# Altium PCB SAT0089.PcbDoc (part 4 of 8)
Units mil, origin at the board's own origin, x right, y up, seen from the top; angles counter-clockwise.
Board outline 4075 x 2715 mil, 6 copper layers (Top Layer, InternalPlane1, MidLayer1, Internal Plane 3, InternalPlane2, Bottom Layer), stack 67.4 mil thick; 538 components, 405 nets, 1716 pads, 1236 vias.
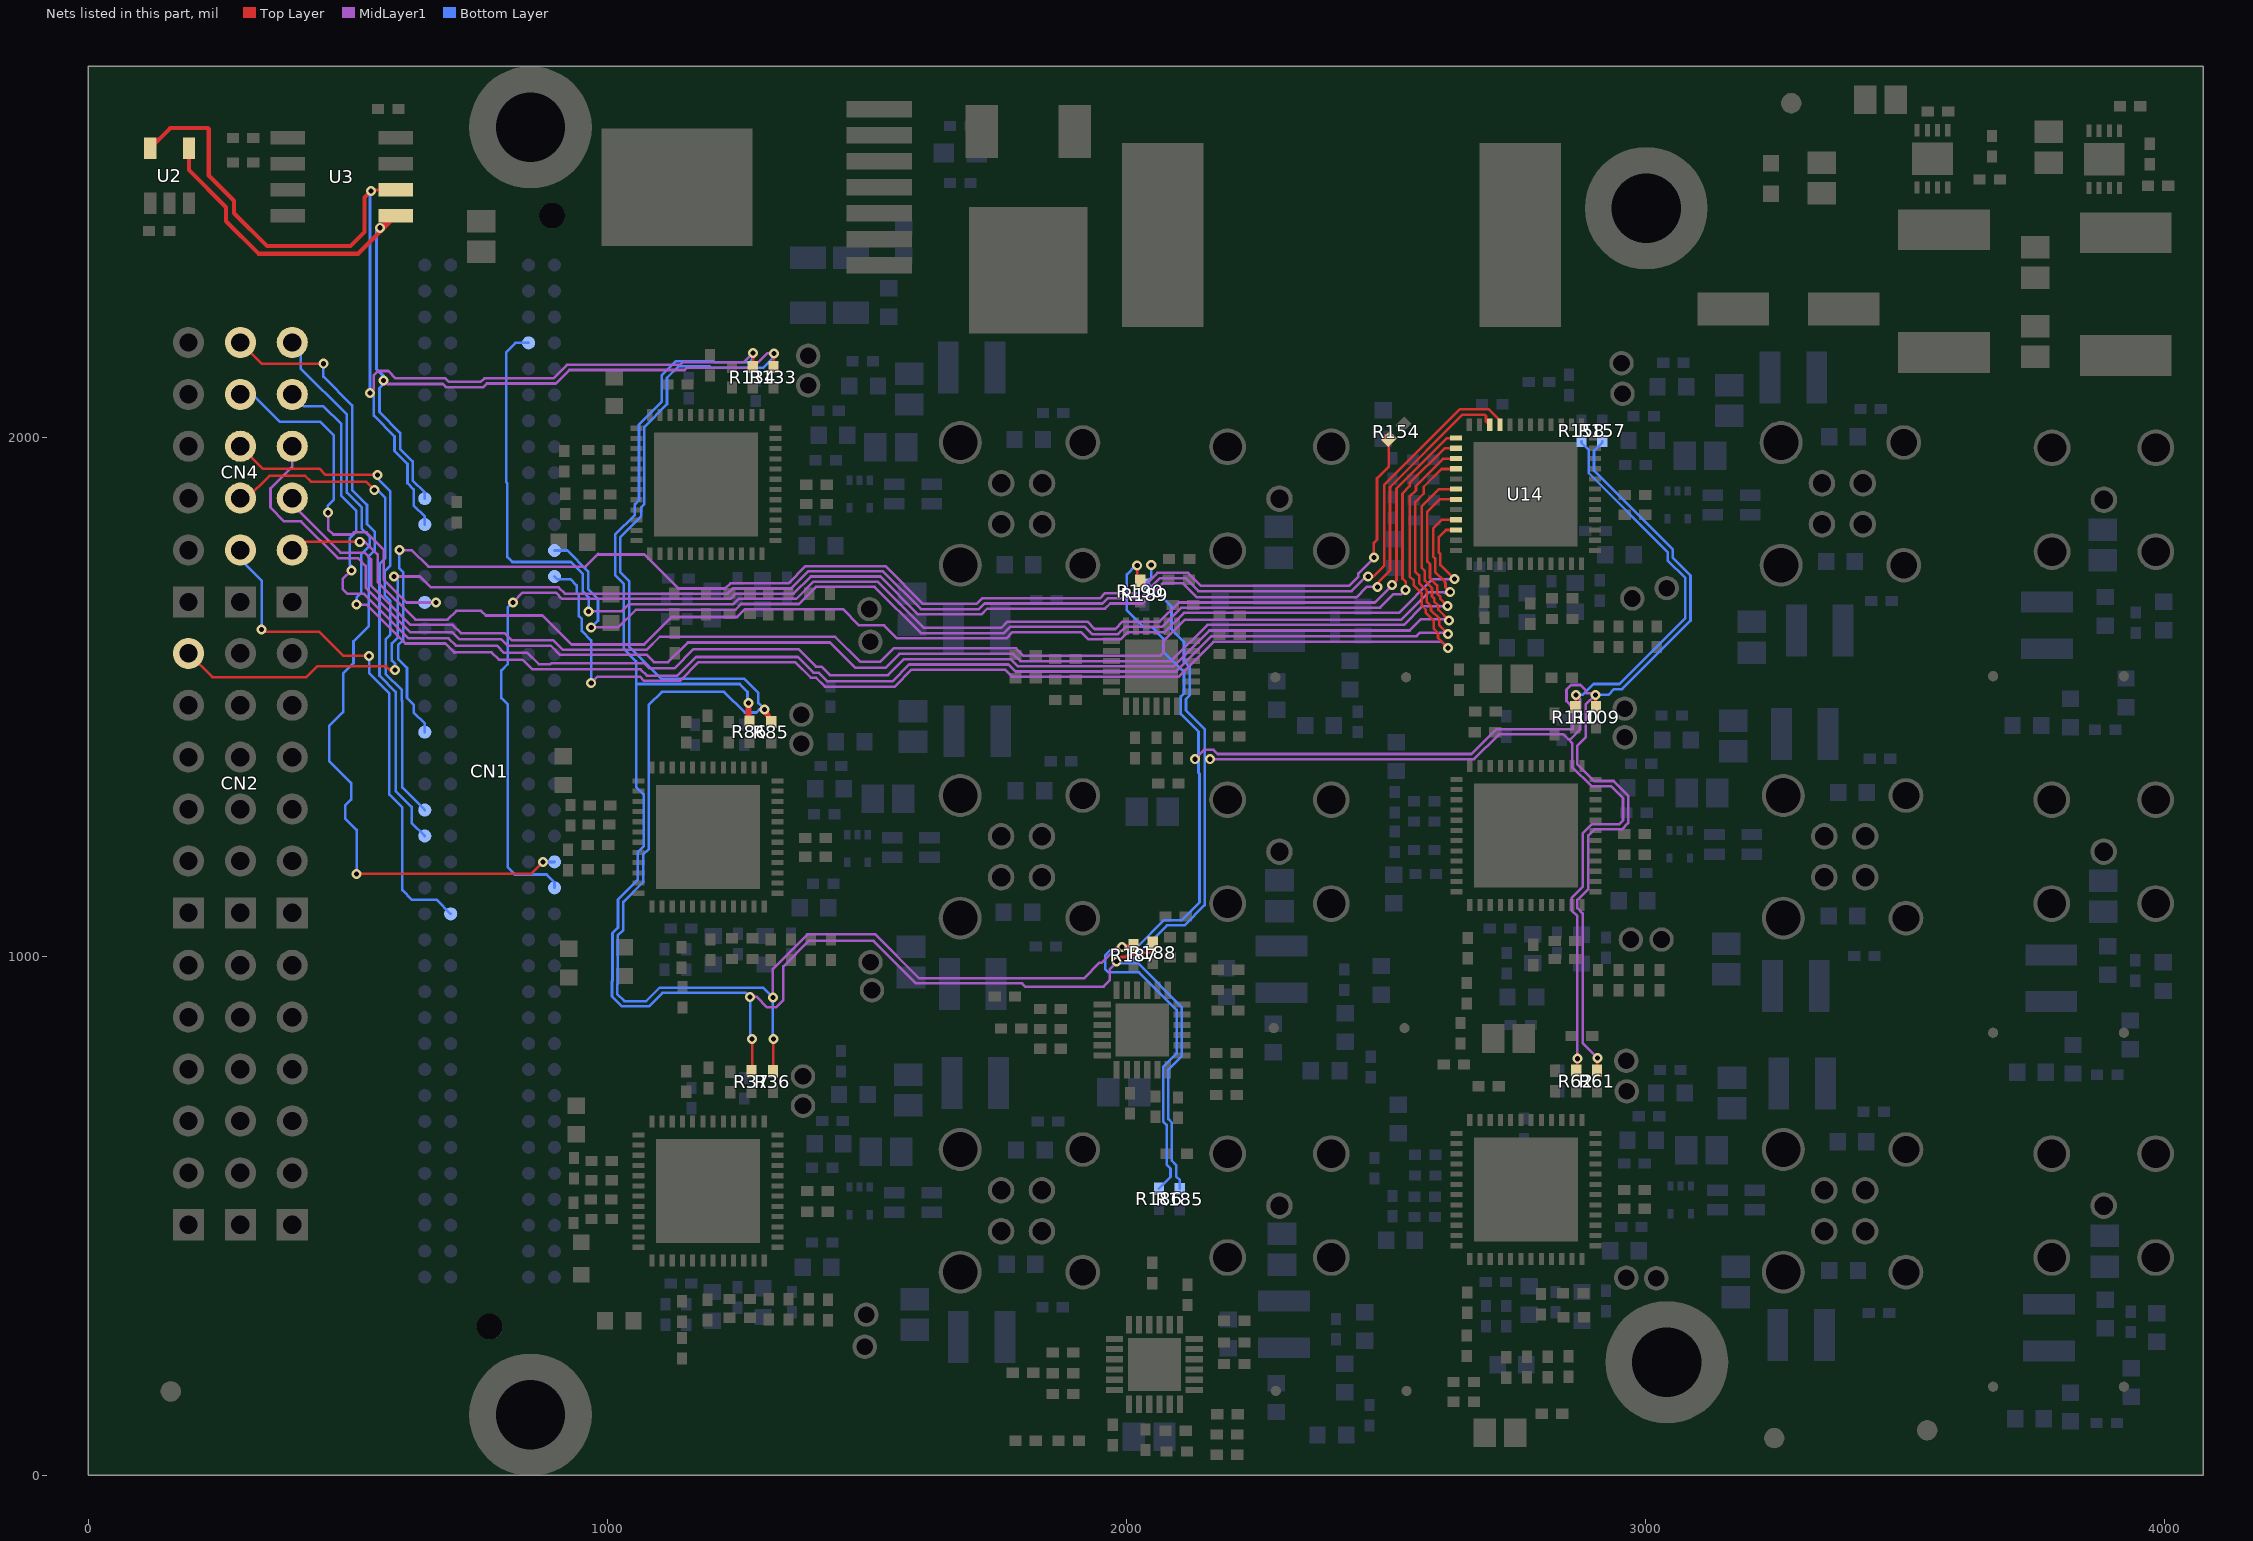
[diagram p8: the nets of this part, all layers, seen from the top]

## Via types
v1: diameter 19.29, hole 9.84, Top Layer to Bottom Layer, tented both sides, 1155 vias
v2: diameter 19.68, hole 7.87, Top Layer to Bottom Layer, tented both sides, 80 vias
v3: diameter 22, hole 10, Top Layer to Bottom Layer, tented both sides, 1 vias

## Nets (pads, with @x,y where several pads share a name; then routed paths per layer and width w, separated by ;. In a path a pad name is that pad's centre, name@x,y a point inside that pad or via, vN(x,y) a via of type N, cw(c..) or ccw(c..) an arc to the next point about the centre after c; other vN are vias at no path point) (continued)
CAM6_D2: CN4.2 U14.22 | length 2617.3
  Top Layer w5: CN4.2@393,1783 407,1797 CN4.2@407,1799 ; CN4.2@407,1800 CN4.2@407,1799 ; v1(523,1799) CN4.2@407,1799 ; v1(2632,1727) 2605,1754 2605,1775 2602,1778 2602,1808 2615.63,1821.63 U14.22@2635.14,1821.63
  MidLayer1 w5: v1(523,1799) 533,1799 557.5,1774.5 557.5,1721.5 630,1649 692,1649 709,1666 757,1666 766,1657 875,1657 931,1601 1071,1601 1124,1654 1250,1654 1265,1669 1454,1669 1485,1638 1533,1638 1558,1613 1769,1613 1781,1625 1913,1625 1927,1611 1989,1611 2003,1625 2074,1625 2111,1662 2525,1662 2590,1727 v1(2632,1727)
CAM6_D2_CAM3_D10: CN1.55 CN4.8 | length 987.9
  Top Layer w5: v1(334,1630) 338,1626 444.5,1626 491.5,1579 v1(541,1579)
  Bottom Layer w5: CN4.8@293,1783 293,1765 334,1724 v1(334,1630) ; v1(541,1579) 541,1546 580,1507 580,1312 605,1287 605,1128 624,1109 671.43,1109 CN1.55@698.27,1082.17
CAM6_D3: CN4.3 U14.21 | length 2697.7
  Top Layer w5: v1(2624,1702) 2615,1711 2615,1719 2614,1720 2614,1722 2595,1741 2595,1767 2591,1771 2591,1825 2607.32,1841.32 U14.21@2635.14,1841.31
  MidLayer1 w5: CN4.3@393,1883 393,1871 486,1778 532,1778 545,1765 545,1715 621,1639 702,1639 718,1623 802,1623 816,1609 896,1609 914,1591 1076,1591 1101,1616 1439,1616 1487,1568 1526,1568 1551.5,1593.5 1787.5,1593.5 1802,1579 2065,1579 2072,1586 2072,1608 2113,1649 2530,1649 2583,1702 v1@2621,1702 ; v1@2615,1700 2619,1700 v1@2621,1702 ; v1@2621,1702 v1(2624,1702) 2624,1703 2622,1703 v1@2621,1702
CAM6_D3_CAM3_D11: CN1.18 CN4.9 | length 1006.7
  Top Layer w5: CN4.9@293,1883 306,1883 349,1926 418,1926 429,1915 535,1915 v1(551,1899)
  Bottom Layer w5: v1(551,1899) 557,1899 572,1884 572,1767 561,1756 561,1541 592,1510 592,1319 623,1288 623,1257.43 CN1.18@648.27,1232.17
CAM6_D4: CN4.4 U14.19 | length 2917.5
  Top Layer w5: v1(2619,1675) 2604.5,1689.5 2604.5,1693.5 2599,1699 2599,1715 2585,1729 2585,1756 2580,1761 2580,1857 2603.68,1880.68 U14.19@2635.14,1880.68
  MidLayer1 w5: CN4.4@393,1983 393,1944 351,1902 351,1865 377.5,1838.5 410,1838.5 481,1767.5 519.5,1767.5 534.5,1752.5 534.5,1710.5 620,1625 701,1625 715,1611 796,1611 808,1599 891,1599 909,1581 1076,1581 1090,1567 1117,1567 1155,1605 1429,1605 1478,1556 1536,1556 1563,1583 1782,1583 1796,1569 2086,1569 2156,1639 2535,1639 2571,1675 v1(2619,1675) v1@2619,1676 ; v1@2615,1676 v1@2619,1676 ; v1@2620,1676 v1@2619,1676
CAM6_D4_CAM4_VS: CN1.19 CN4.10 | length 987
  Top Layer w5: CN4.10@293,1983 336,1940 445,1940 457,1928 v1(557,1928)
  Bottom Layer w5: v1(557,1928) 557,1921 582,1896 582,1753 571,1742 571,1696 582,1685 582,1620 573,1611 573,1544 604,1513 604,1493 605,1492 605,1325.43 CN1.19@648.27,1282.17
CAM6_D5: CN4.5 U14.18 | length 3076.2
  Top Layer w5: v1(2622,1647) 2601,1668 2601,1676 2593,1684 2593,1690 2589,1694 2589,1710 2575,1724 2575,1743 2569,1749 2569,1867 2601.84,1899.84 2635.14,1899.84 U14.18@2635.14,1900.37
  MidLayer1 w5: v1(507,1744) 490,1727 490,1708 499.5,1698.5 531.5,1698.5 617,1613 694,1613 708,1599 787,1599 801,1585 846,1585 868,1563 890,1563 892,1565 1071,1565 1081,1555 1129,1555 1166,1592 1368.5,1592 1402,1558.5 1412.5,1558.5 1429,1542 1541,1542 1572,1573 1777,1573 1791,1559 2091,1559 2160,1628 2546,1628 2568,1650 2619,1650 v1@2621,1648 ; v1@2621,1648 v1(2622,1647) 2622,1648 v1@2621,1648
  Bottom Layer w5: CN4.5@393,2083 416,2060 453,2060 487.5,2025.5 487.5,1887.5 516.5,1858.5 516.5,1818.5 504,1806 504,1755 507,1752 v1(507,1744)
CAM6_D5_CAM4_D10: CN1.27 CN4.11 | length 724.6
  MidLayer1 w5: v1(462,1855) 462,1823 472,1813 508,1813 512,1817 536,1817 569,1784 569,1726 613,1682 v1(670,1682)
  Bottom Layer w5: CN4.11@293,2083 316,2083 369,2030 447,2030 473,2004 473,1880 461,1868 461,1856 v1(462,1855) ; CN1.27@648.27,1682.17 669.83,1682.17 v1(670,1682)
CAM6_D6: CN4.6 U14.16 | length 3216.5
  Top Layer w5: v1(2620,1621) 2603,1638 2603,1651 2587,1667 2587,1675 2579,1683 2579,1705 2564,1720 2564,1734 2557,1741 2557,1876 2573,1892 2573,1905 2607.21,1939.21 2635.14,1939.21 U14.16@2635.14,1939.74
  MidLayer1 w5: v1(517,1678) 536,1678 611,1603 688,1603 705.5,1585.5 706,1586 777,1586 791,1572 837,1572 856,1553 1064,1553 1076,1541 1135,1541 1171,1577 1367,1577 1397,1547 1407,1547 1424,1530 1549,1530 1581.5,1562.5 1773,1562.5 1786.5,1549 2096,1549 2164,1617 2559,1617 2566,1624 2617,1624 v1(2620,1621)
  Bottom Layer w5: CN4.6@393,2183 409,2167 409,2133 498,2044 498,1894 527,1865 527,1824 542,1809 542,1791 526,1775 526,1701 517,1692 v1(517,1678)
CAM6_D6_CAM4_D11: CN1.137 CN4.12 | length 1659.8
  Top Layer w5: CN4.12@293,2183 334,2142 v1(453,2142) ; v1(517,1159) 853,1159 v1(876,1182)
  Bottom Layer w5: v1(453,2142) 453,2117 508.5,2061.5 508.5,1898.5 537,1870 537,1833 552,1818 552,1783 540,1771 540,1636 511,1607 511,1565 491,1545 491,1471 464,1444 464,1377 506.5,1334.5 506.5,1302.5 495,1291 495,1266 517,1244 v1(517,1159) ; v1(876,1182) 898.1,1182 CN1.137@898.27,1182.17
CAM6_D7: CN1.148 U14.15 | length 2442.6
  Top Layer w5: v1(2620,1594) 2600.5,1613.5 2600.5,1623 2592,1631.5 2592,1647 2577,1662 2577,1668 2569,1676 2569,1700 2554,1715 2554,1724 2546,1732 2546,1886 2558,1898 2558,1906.9 2610,1958.9 2635.14,1958.9 U14.15@2635.14,1959.43
  MidLayer1 w5: v1(969,1527) 981,1539 1063,1539 1071,1531 1140,1531 1176,1567 1362,1567 1392,1537 1402,1537 1419,1520 1554,1520 1586.5,1552.5 1766,1552.5 1779.5,1539 2101,1539 2168,1606 2608,1606 v1(2620,1594)
  Bottom Layer w5: CN1.148@898.27,1732.17 903.43,1727 929,1727 941,1715 941,1700 945,1696 945,1656 951,1650 951,1627 969,1609 v1(969,1527)
CAM6_D8: CN1.149 U14.14 | length 2218
  Top Layer w5: v1(2538,1706) 2538,1722 2532,1728 2532,1892 2546,1906 2546,1912 2613.11,1979.11 U14.14@2635.14,1979.11
  MidLayer1 w5: v1(969,1634) 1021,1634 1055,1668 1247,1668 1258,1679 1369,1679 1402,1712 1515,1712 1604,1623 1764,1623 1776,1635 1920,1635 1934,1621 1984,1621 1998,1635 2069,1635 2106,1672 2489,1672 2515,1698 2530,1698 v1(2538,1706)
  Bottom Layer w5: CN1.149@898.27,1782.17 922.83,1782.17 963,1742 963,1708 982,1689 982,1647 v1(969,1634)
CAM6_D9: CN1.117 U14.13 | length 2680.8
  Top Layer w5: v1(2512,1716) 2520.5,1724.5 2520.5,1901.5 2617.8,1998.8 U14.13@2635.14,1998.8
  MidLayer1 w5: v1(964,1665) 1027.5,1665 1041,1678.5 1242.5,1678.5 1253,1689 1364,1689 1397,1722 1521,1722 1610,1633 1759,1633 1771,1645 1925,1645 1939,1631 1979,1631 1993,1645 2064,1645 2101,1682 2479,1682 2512,1715 v1(2512,1716)
  Bottom Layer w5: CN1.117@848.27,2182.17 823.17,2182.17 805,2164 805,1914 807.5,1911.5 807.5,1769.5 817,1760 930,1760 953,1737 953,1703 964,1692 v1(964,1665)
CAM6_HS: CN1.136 U14.10 | length 2881.5
  Top Layer w5: v1(2484,1712) 2484,1720 2508,1744 2508,1905 2509,1905 2648,2044 2690,2044 2693,2041 2693,2030.96 2699.84,2024.12 2700.1,2023.86 U14.10@2700.1,2024.39
  MidLayer1 w5: v1(818,1682) 837,1701 901,1701 913,1689 1237,1689 1247,1699 1359,1699 1392,1732 1526,1732 1599,1659 1721,1659 1732,1670 1959,1670 1969,1680 2031,1680 2070,1719 2109,1719 2136,1692 2443,1692 2463,1712 v1(2484,1712) 2484,1709 v1@2486,1707
  Bottom Layer w5: v1(818,1682) 808,1672 808,1563 796,1551 796,1498 808,1486 808,1172 822,1158 883,1158 898.27,1142.73 CN1.136@898.27,1132.17
CAM6_PCLK: CN1.22 R154.1 | length 2681.9
  Top Layer w5: v1@2475,1771 v1(2477,1769) ; v1@2479,1765 2478,1764 2474,1764 2477,1767 v1(2477,1769) ; R154.1@2499,2003.72 2505.86,1996.86 2505.86,1943.86 2483,1921 2483,1803 2477,1797 v1(2477,1769)
  MidLayer1 w5: v1(599.5,1783) 623,1783 655,1751 958,1751 982.5,1775.5 983.5,1774.5 1071.5,1774.5 1137,1709 1227,1709 1237,1719 1349,1719 1382,1752 1536,1752 1608.5,1679.5 1711.5,1679.5 1722,1690 1949,1690 1959,1700 2021,1700 2060,1739 2119,1739 2144,1714 2429,1714 2447,1732 2447,1738 2477,1768 v1(2477,1769)
  Bottom Layer w5: v1(599.5,1783) 599.5,1782.5 599,1782 599,1748 607,1740 607,1610 597,1600 597,1573 614,1556 614,1498 627,1485 627,1470 648.27,1448.73 CN1.22@648.27,1432.17
CAM6_VS: CN2.18 U14.9 | length 3102.5
  Top Layer w5: v1(591,1552) 581,1552 574,1559 441,1559 420,1538 239,1538 CN2.18@194,1583 ; v1(2466,1732) 2476,1732 2497,1753 2497,1909 2642.5,2054.5 2697.5,2054.5 2719.79,2032.21 U14.9@2719.79,2024.39 U14.9@2719.79,2023.86 ; CN2.18@194,1583 CN2.18@193,1584 193,1583 CN2.18@194,1583
  MidLayer1 w5: v1(589,1732) 639,1732 660,1711 906,1711 918,1699 1232,1699 1242,1709 1354,1709 1387,1742 1531,1742 1604,1669 1716,1669 1727,1680 1954,1680 1964,1690 2026,1690 2065,1729 2114,1729 2139,1704 2434,1704 2462,1732 v1(2466,1732)
  Bottom Layer w5: v1(589,1732) 596,1725 596,1614 585,1603 585,1570 591,1564 v1(591,1552)
CAM_SCL: CN1.30 R37.1 R62.1 R86.1 R110.1 R134.1 R158.1 R185.2 R188.2 R189.2 U2.5 U3.6 | length 9197.2
  Top Layer w5: R37.1@1278,779 1276,781 1279,784 v1(1279,841) ; R134.1@1280,2136 1281,2137 v1(1281,2163) ; v1(1981,990) 1990,999 1998,999 2001,1002 2029,1002 2034.5,1007.5 2047.5,1007.5 2053,1013 2053,1025 R188.2@2051,1027 ; R110.1@2865,1481 2866,1482 v1(2866,1504) ; R62.1@2867,780 2869,782 v1(2869,803)
  Top Layer w6: v1(545,2475) 547.05,2477.05 U3.6@593.21,2477.05
  Top Layer w8: U2.5@119.13,2555.2 119.13,2557.13 158,2596 230,2596 232,2594 232,2505 281,2456 281,2432 344,2369 505,2369 532,2396 532,2462 v1(545,2475)
  Top Layer w11.02: v1(1272,1488) 1272,1454 R86.1@1274,1452
  MidLayer1 w5: v1(543,2086) 550,2093 550,2120 558,2128 578,2128 592,2114 688,2114 695,2107 756,2107 763,2114 896,2114 922,2140 1140,2140 1144.5,2144.5 1262.5,2144.5 v1(1281,2163) ; v1(1275,922) 1288,922 1308,902 1325,902 1339,916 1339,981 1388,1030 1513,1030 1595,948 1799,948 1805,942 1956,942 1968,954 1968,975 1981,988 v1(1981,990) ; v1(2161,1380) 2670,1380 2718,1428 2842,1428 2851.5,1418.5 ; v1(2866,1504) 2874,1496 2874,1437 2855.5,1418.5 2851.5,1418.5 ; v1(2869,803) 2869,1078 2858,1089 2858,1113 2879,1134 2879,1237 2897,1255 2950,1255 2957,1262 2957,1305 2934,1328 2896,1328 2859,1365 2859,1411 2851.5,1418.5
  Bottom Layer w5: v1(543,2086) 550,2079 550,2042 590,2002 590,1974 615,1949 615,1912 627,1900 627,1869 648.27,1847.73 CN1.30@648.27,1832.17 ; v1(1272,1488) 1270,1490 1270,1510 1255,1525 1055.5,1525 ; v1(1279,841) 1275,845 v1(1275,922) 1267,930 1106,930 1080,904 1028,904 1009,923 1009,952 1010,953 1010,1045 1020.5,1055.5 1020.5,1109.5 1059,1148 1059,1201 1070,1212 1070,1312 1055.5,1326.5 1055.5,1525 ; v1(1281,2163) 1279,2161 1279,2150 1273.5,2144.5 1206.5,2144.5 1204,2147 1132,2147 1105,2120 1105,2069 1061,2025 1061,1879 1053,1871 1053,1851 1015,1813 1015,1735 1032,1718 1032,1592 1055.5,1568.5 1055.5,1525 ; v1(1981,990) 1983,990 1986,987 2005,987 ; v1(2048,1754) 2048,1730 2035,1717 2044,1717 2087,1674 2087,1630 2111,1606 2111,1569 2122,1558 2122,1503 2115,1496 2115,1474 2151,1438 2151,1381 ; R185.2@2103,552.5 2103,569.5 2096,576.5 2096,598 2087.5,606.5 2087.5,680 2081,686.5 2081,782 2107,808 2107,902 2022,987 2005,987 ; v1(2161,1380) 2162,1381 2151,1381 ; v1(2866,1504) 2879,1504 2900,1525 2950,1525 3077,1652 3077,1729 3043,1763 3043,1779 2891,1931 2891,1975.5 2877,1989.5 R158.1@2877,1993 ; 2005,987 2078,1060 2112,1060 2151,1099 2151,1381
  Bottom Layer w6: v1(543,2086) 543,2473 v1(545,2475)
CAM_SDA: CN1.31 R36.2 R61.2 R85.2 R109.2 R133.2 R157.2 R186.2 R187.2 R190.2 U2.4 U3.5 | length 9319.1
  Top Layer w5: R36.2@1319,779 1322,782 1320,784 v1(1320,841) ; R133.2@1320,2136 1321,2137 v1(1321,2162) ; v1(1992,1018) 1995,1021 R187.2@2014,1021 ; v1(2021,1753) 2021,1727 2024,1724 R190.2@2027,1724 ; v1(2904,1504) 2904,1482 R109.2@2905,1481 ; R61.2@2907,780 2907,803 v1(2908,804)
  Top Layer w6: v1(562,2404) 585.05,2427.05 U3.5@593.21,2427.05
  Top Layer w8: U2.4@193.94,2555.2 193.94,2515.06 265.5,2443.5 265.5,2416.5 328,2354 520.17,2354 U3.5@593.21,2427.05
  Top Layer w11.02: v1(1303,1476) R85.2@1316,1452
  MidLayer1 w5: v1(569,2110) 576,2103 683,2103 689,2097 761,2097 768,2104 901,2104 927,2130 1149,2130 1153,2134 1280,2134 1308,2162 v1(1321,2162) ; v1(1319,921) 1319,976 1385.5,1042.5 1516.5,1042.5 1601,958 1918,958 1948,988 1953,988 1983,1018 v1(1992,1018) ; v1(2132,1380) 2150,1398 2168,1398 2176,1390 2665,1390 2713,1438 2860,1438 2860,1480 2848,1492 2848,1514 2857,1523 2875,1523 2886,1512 2886,1507 2901,1507 v1(2904,1504) 2885,1485 2885,1422 2869,1406 2869,1370 2901,1338 2939,1338 2967,1310 2967,1257 2955,1245 2902,1245 2890,1233 2890,1130 2869,1109 2869,1093 2879,1083 2879,833 v1(2908,804)
  Bottom Layer w5: v1(569,2110) 569,2103 561,2095 561,2049 601,2009 601,1978 625,1954 625,1917 648.27,1893.73 CN1.31@648.27,1882.17 ; v1@1319,841 v1(1320,841) 1319,842 v1(1319,921) 1300,940 1101,940 1075,914 1033,914 1019,928 1019,946 1020,947 1020,1040 1031,1051 1031,1105 1069,1143 1069,1196 1080,1207 1080,1485 1105,1510 1225,1510 1265,1470 1287,1470 1293,1476 v1(1303,1476) 1291,1488 1291,1508 1264,1535 1104,1535 1042,1597 1042,1723 1025,1740 1025,1808 1065,1848 1065,1865 1071.5,1871.5 1071.5,2020.5 1115,2064 1115,2115 1137,2137 1197,2137 1200,2134 1300,2134 1321,2155 v1(1321,2162) ; v1(2021,1753) 2018,1753 2001,1736 2001,1667 2034,1634 2050,1634 2071,1613 2071,1588 2111,1548 2111,1507 2105,1501 2105,1467 2139,1433 v1@2139,1381 ; R186.2@2063,553 2085,575 2085,591.5 2077.5,599 2077.5,675.5 2071,682 2071,787 2097,813 2097,897 2024.5,969.5 1965.5,969.5 1959,976 1959,1002 1969,1012 1986,1012 v1(1992,1018) 2021,1018 2073,1070 2107,1070 2141,1104 2141,1352 2139,1354 v1@2139,1381 ; v1(2132,1380) 2133,1381 v1@2139,1381 ; v1(2904,1504) 2929,1504 2940,1515 2955,1515 3087,1647 3087,1734 3053,1768 3053,1784 2901,1936 2901,1974 2917,1990 R157.2@2917,1993
  Bottom Layer w6: v1(562,2404) 555,2397 555,2132 569,2118 v1(569,2110)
